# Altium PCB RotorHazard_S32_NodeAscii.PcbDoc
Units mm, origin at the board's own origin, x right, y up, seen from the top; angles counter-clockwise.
Board outline 34.29 x 33.02 mm, 2 copper layers (Top Layer, Bottom Layer); 2 components, 6 nets, 21 pads, 0 vias.
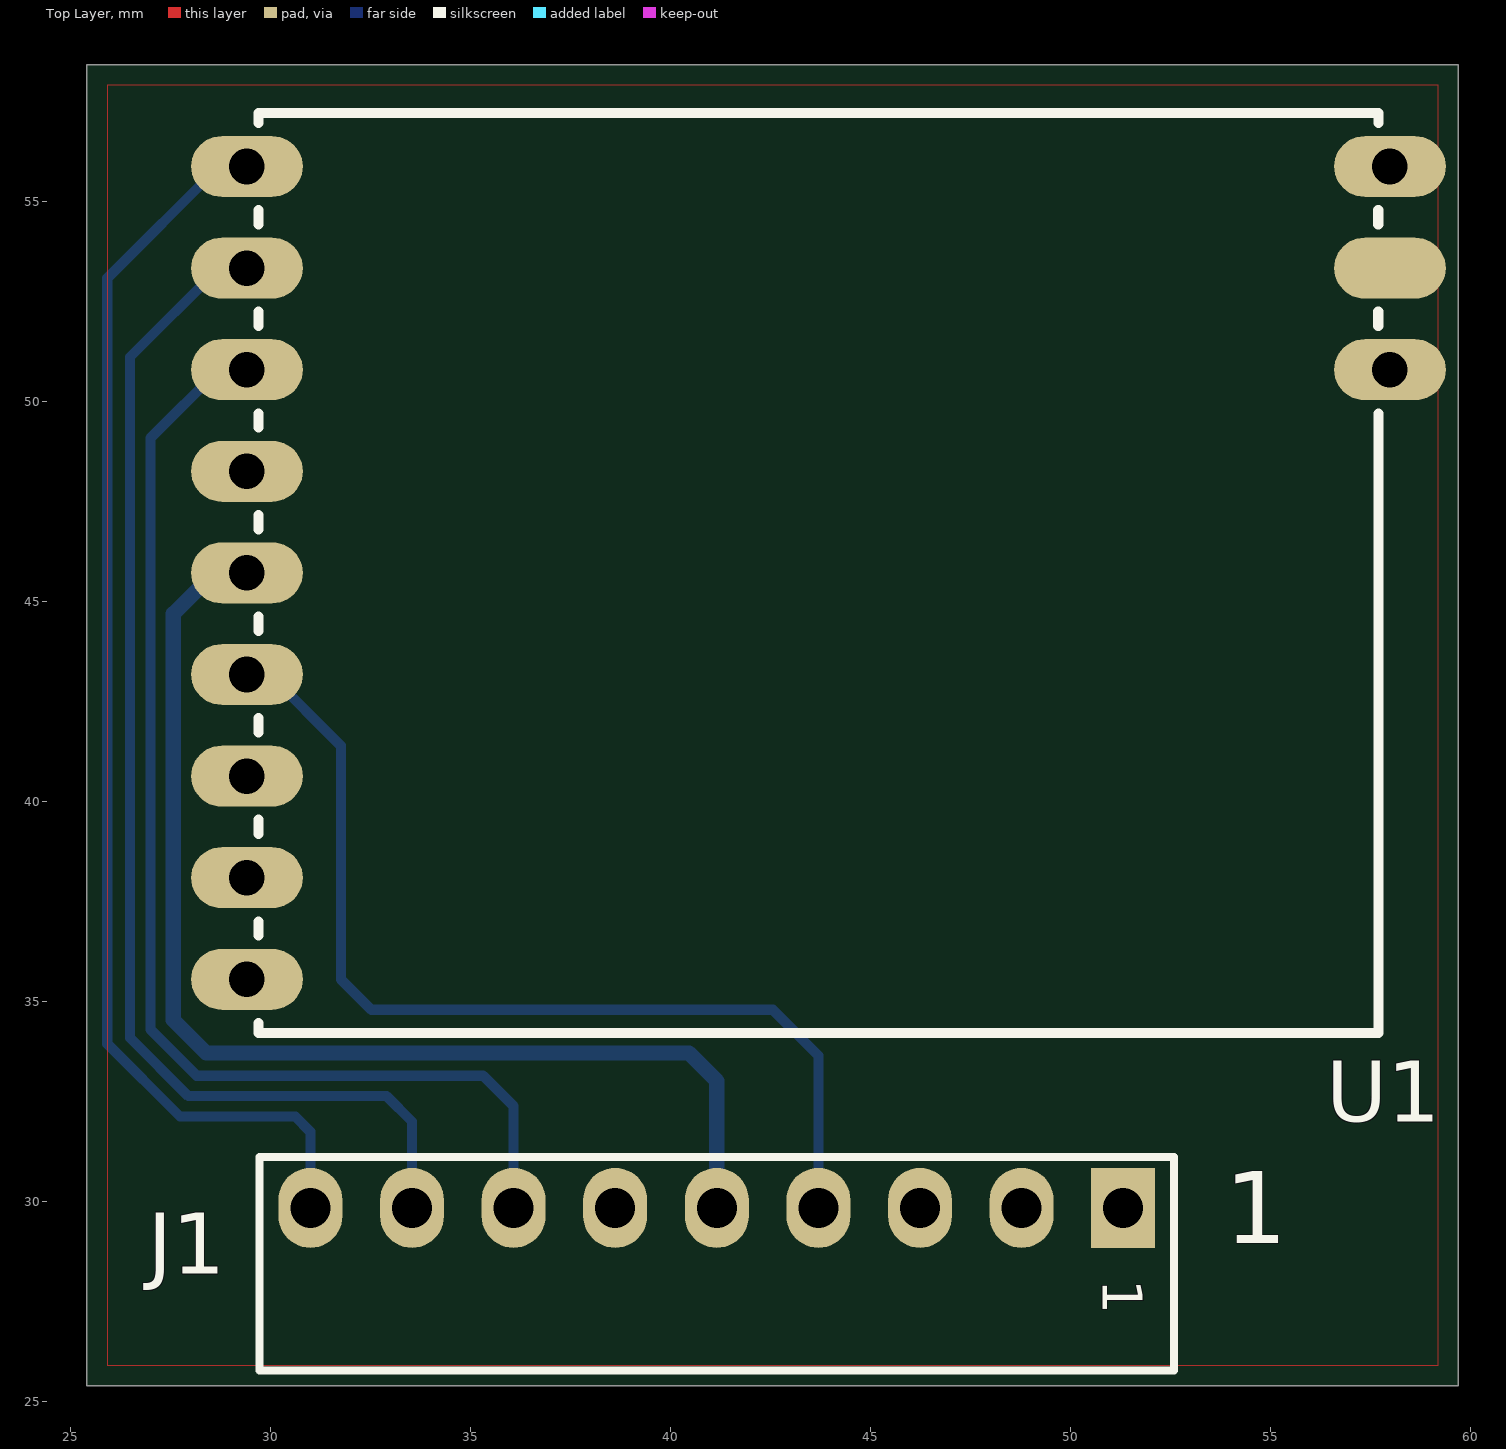
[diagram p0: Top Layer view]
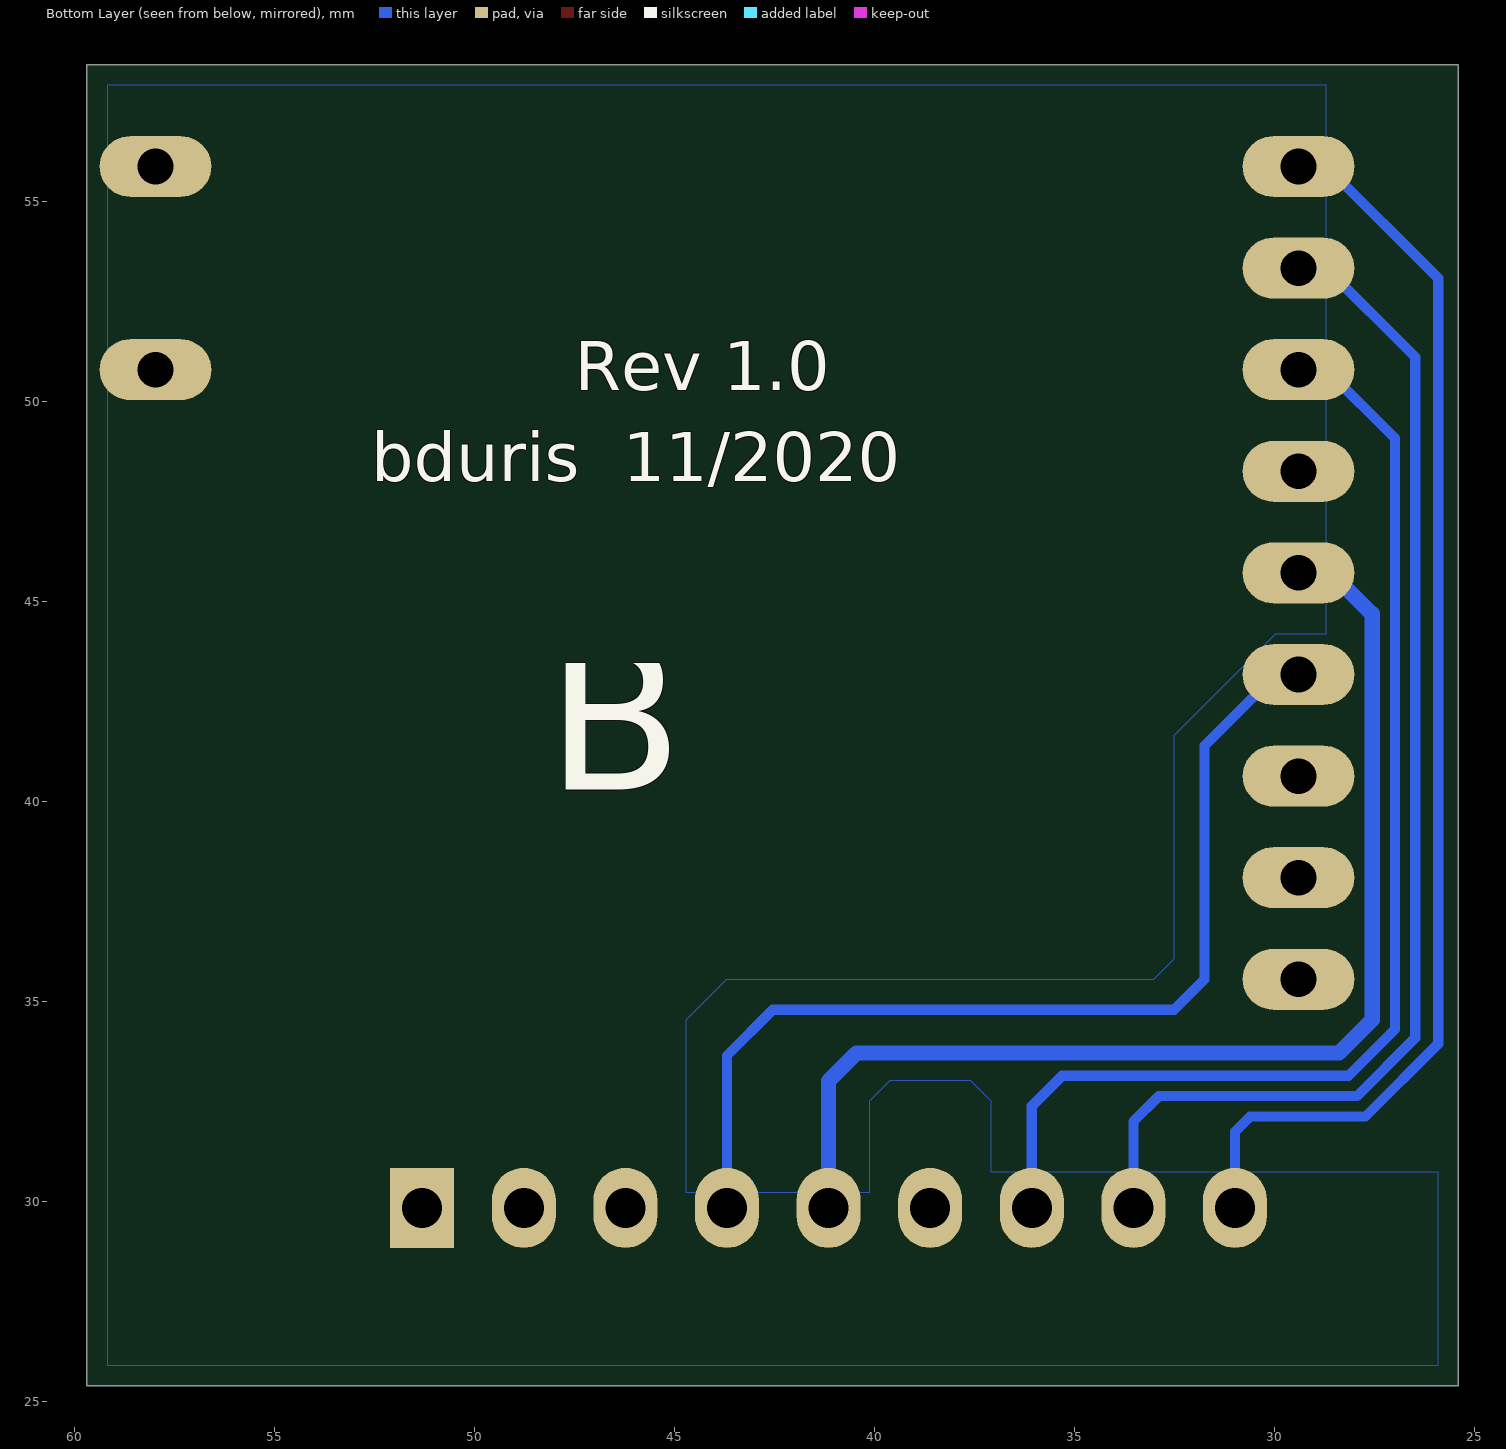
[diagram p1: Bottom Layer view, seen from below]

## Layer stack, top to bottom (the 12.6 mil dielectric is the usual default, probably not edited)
Top Solder: solder mask 0.0102, Solder Resist, Dk 3.5
Top Layer: signal copper 0.0356
Dielectric 1: dielectric 0.32, FR-4, Dk 4.8
Bottom Layer: signal copper 0.0356
Bottom Solder: solder mask 0.0102, Solder Resist, Dk 3.5

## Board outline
25.4,25.4 59.69,25.4 59.69,58.42 25.4,58.42

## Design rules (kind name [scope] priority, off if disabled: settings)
AssemblyTestPointUsage [All] p0: scope1count=1 scope1_0_kind=Board scope1_0_value=Board scope2count=1 scope2_0_kind=Board scope2_0_value=Board commentlength=0
AssemblyTestpoint [All] p0: scope1count=1 scope1_0_kind=Board scope1_0_value=Board scope2count=1 scope2_0_kind=Board scope2_0_value=Board commentlength=0
Clearance [All] p0: scope1count=1 scope1_0_kind=Board scope1_0_value=Board scope2count=1 scope2_0_kind=Board scope2_0_value=Board commentlength=0 gap=0.254
Clearance [All] p1: gap=0.254
ComponentClearance [All] p0: scope1count=1 scope1_0_kind=Board scope1_0_value=Board scope2count=1 scope2_0_kind=Board scope2_0_value=Board commentlength=0 gap=0.254 collisioncheckmode=3
DiffPairsRouting [All] p0: scope1count=1 scope1_0_kind=Board scope1_0_value=Board scope2count=1 scope2_0_kind=Board scope2_0_value=Board commentlength=0
FabricationTestPointUsage [All] p0: scope1count=1 scope1_0_kind=Board scope1_0_value=Board scope2count=1 scope2_0_kind=Board scope2_0_value=Board commentlength=0 valid=0 allowmultiple=FALSE
FabricationTestpoint [All] p0: scope1count=1 scope1_0_kind=Board scope1_0_value=Board scope2count=1 scope2_0_kind=Board scope2_0_value=Board commentlength=0 side=3 testpointundercomponent=TRUE minsize=1.016 maxsize=2.54 preferedsize=1.524 minholesize=0 maxholesize=1.016 preferedholesize=0.813 testpointgrid=0.025
FanoutControl Fanout_Default [All] p0: scope1count=1 scope1_0_kind=Board scope1_0_value=Board scope2count=1 scope2_0_kind=Board scope2_0_value=Board commentlength=30 // Fanout_Default (Default Rule)
FanoutControl Fanout_Small [All] p0 off: scope1count=1 scope1_0_kind=Board scope1_0_value=Board scope2count=1 scope2_0_kind=Board scope2_0_value=Board commentlength=84 // Protel DXP Scope 1 Expression Was: (CompPinCount < 5)   Fanout_Small (Default Rule)
FanoutControl Fanout_SOIC [All] p0 off: scope1count=1 scope1_0_kind=Board scope1_0_value=Board scope2count=1 scope2_0_kind=Board scope2_0_value=Board commentlength=71 // Protel DXP Scope 1 Expression Was: IsSOIC   Fanout_SOIC (Default Rule)
FanoutControl Fanout_LCC [All] p0 off: scope1count=1 scope1_0_kind=Board scope1_0_value=Board scope2count=1 scope2_0_kind=Board scope2_0_value=Board commentlength=69 // Protel DXP Scope 1 Expression Was: IsLCC   Fanout_LCC (Default Rule)
FanoutControl Fanout_BGA [All] p0 off: scope1count=1 scope1_0_kind=Board scope1_0_value=Board scope2count=1 scope2_0_kind=Board scope2_0_value=Board commentlength=69 // Protel DXP Scope 1 Expression Was: IsBGA   Fanout_BGA (Default Rule)
Height [All] p0: scope1count=1 scope1_0_kind=Board scope1_0_value=Board scope2count=1 scope2_0_kind=Board scope2_0_value=Board commentlength=0
HoleSize [All] p0: scope1count=1 scope1_0_kind=Board scope1_0_value=Board scope2count=1 scope2_0_kind=Board scope2_0_value=Board commentlength=0 absolutevalues=TRUE maxlimit=2.54 minlimit=0.025 maxpercent=80.000 minpercent=20.000
HoleToHoleClearance [All] p0: scope1count=1 scope1_0_kind=Board scope1_0_value=Board scope2count=1 scope2_0_kind=Board scope2_0_value=Board commentlength=0
LayerPairs [All] p0: scope1count=1 scope1_0_kind=Board scope1_0_value=Board scope2count=1 scope2_0_kind=Board scope2_0_value=Board commentlength=0 enforce=TRUE
MinimumSolderMaskSliver [All] p0: scope1count=1 scope1_0_kind=Board scope1_0_value=Board scope2count=1 scope2_0_kind=Board scope2_0_value=Board commentlength=0
NetAntennae [All] p0: scope1count=1 scope1_0_kind=Board scope1_0_value=Board scope2count=1 scope2_0_kind=Board scope2_0_value=Board commentlength=0
PasteMaskExpansion [All] p0: scope1count=1 scope1_0_kind=Board scope1_0_value=Board scope2count=1 scope2_0_kind=Board scope2_0_value=Board commentlength=0 expansion=0
PlaneClearance [All] p0: scope1count=1 scope1_0_kind=Board scope1_0_value=Board scope2count=1 scope2_0_kind=Board scope2_0_value=Board commentlength=0 clearance=0.508
PlaneConnect [All] p0: scope1count=1 scope1_0_kind=Board scope1_0_value=Board scope2count=1 scope2_0_kind=Board scope2_0_value=Board commentlength=0 planeconnectstyle=Relief reliefexpansion=0.508 reliefentries=4 reliefconductorwidth=0.254 reliefairgap=0.254
PolygonConnect [All] p0: scope1count=1 scope1_0_kind=Board scope1_0_value=Board scope2count=1 scope2_0_kind=Board scope2_0_value=Board commentlength=0 connectstyle=Relief reliefconductorwidth=0.254 reliefentries=4 polygonreliefangle="90 Angle"
PolygonConnect [All] p1: connectstyle=Relief reliefconductorwidth=0.254 reliefentries=4 polygonreliefangle="90 Angle" airgapwidth=0.254
RoutingCorners [All] p0: scope1count=1 scope1_0_kind=Board scope1_0_value=Board scope2count=1 scope2_0_kind=Board scope2_0_value=Board commentlength=0 cornerstyle=45-Degree minsetback=2.54 maxsetback=2.54
RoutingLayers [All] p0: scope1count=1 scope1_0_kind=Board scope1_0_value=Board scope2count=1 scope2_0_kind=Board scope2_0_value=Board commentlength=0 top layer=Automatic bottom layer=Automatic
RoutingPriority [All] p0: scope1count=1 scope1_0_kind=Board scope1_0_value=Board scope2count=1 scope2_0_kind=Board scope2_0_value=Board commentlength=0
RoutingTopology [All] p0: scope1count=1 scope1_0_kind=Board scope1_0_value=Board scope2count=1 scope2_0_kind=Board scope2_0_value=Board commentlength=0 topology=Shortest
RoutingVias [All] p0: scope1count=1 scope1_0_kind=Board scope1_0_value=Board scope2count=1 scope2_0_kind=Board scope2_0_value=Board commentlength=0 holewidth=0.711 width=1.27 viastyle="Through Hole" minholewidth=0.711 minwidth=1.27 maxholewidth=0.711 maxwidth=1.27
RoutingVias [All] p1: holewidth=0.711 width=1.27 viastyle="Through Hole" minholewidth=0.711 minwidth=1.27 maxholewidth=0.711 maxwidth=1.27
ShortCircuit [All] p0: scope1count=1 scope1_0_kind=Board scope1_0_value=Board scope2count=1 scope2_0_kind=Board scope2_0_value=Board commentlength=0 allowed=FALSE
SilkToBoardRegionClearance [All] p0: scope1count=1 scope1_0_kind=Board scope1_0_value=Board scope2count=1 scope2_0_kind=Board scope2_0_value=Board commentlength=0
SilkToSilkClearance [All] p0: scope1count=1 scope1_0_kind=Board scope1_0_value=Board scope2count=1 scope2_0_kind=Board scope2_0_value=Board commentlength=0
SilkToSolderMaskClearance [All] p0 off: scope1count=1 scope1_0_kind=Board scope1_0_value=Board scope2count=1 scope2_0_kind=Board scope2_0_value=Board commentlength=44 // Protel DXP Scope 1 Expression Was: IsPad
SilkToSolderMaskClearance [IsPad] p1: minsilkscreentomaskgap=0.152 clearancetoexposedcopper=TRUE
SolderMaskExpansion [All] p0: scope1count=1 scope1_0_kind=Board scope1_0_value=Board scope2count=1 scope2_0_kind=Board scope2_0_value=Board commentlength=0 expansion=0.102
SolderMaskExpansion [All] p1: expansion=0.102
UnRoutedNet [All] p0: scope1count=1 scope1_0_kind=Board scope1_0_value=Board scope2count=1 scope2_0_kind=Board scope2_0_value=Board commentlength=0
UnpouredPolygon [All] p0: scope1count=1 scope1_0_kind=Board scope1_0_value=Board scope2count=1 scope2_0_kind=Board scope2_0_value=Board commentlength=0
Width [All] p0: scope1count=1 scope1_0_kind=Board scope1_0_value=Board scope2count=1 scope2_0_kind=Board scope2_0_value=Board commentlength=0 maxlimit=0.889 minlimit=0.254 preferedwidth=0.254
Width [All] p1: maxlimit=0.889 minlimit=0.254 preferedwidth=0.254 minimp=50.000000 maximp=50.000000 favimp=50.000000
29 further rules are at their usual default settings.

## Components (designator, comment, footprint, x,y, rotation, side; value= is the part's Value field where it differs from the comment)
J1 "HDR 1X9 RA" "HDR 1X9 2.54mm RA" 51.308,29.845 r270 top
U1 "RX5808" RX5808_MULTI 43.688,45.72 r180 top

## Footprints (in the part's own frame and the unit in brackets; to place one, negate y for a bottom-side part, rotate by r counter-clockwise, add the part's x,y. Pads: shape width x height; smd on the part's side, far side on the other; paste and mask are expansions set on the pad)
"HDR 1X9 2.54mm RA" [mm]
  rect 2x1.6 hole 1: 1(0,0)
  oval 2x1.6 hole 1: 2(0,-2.54) 3(0,-5.08) 4(0,-7.62) 5(0,-10.16) 6(0,-12.7) 7(0,-15.24) 8(0,-17.78) 9(0,-20.32)
  silkscreen extent -1.27,-21.59 4.06,1.27
RX5808_MULTI [mil] "RX5808 Module with multi-layer pads"
  oval 110x60 hole 35: 1(562.5,-400) 2(562.5,-300) 3(562.5,-200) 4(562.5,-100) 5(562.5,0) 6(562.5,100) 7(562.5,200) 8(562.5,300) 9(562.5,400) 10(-562.5,-200) 12(-562.5,-400)
  oval 110x60 smd: 11(-562.5,-300)
  silkscreen extent -551,-453 551,453

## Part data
J1: library part 649-1012937990904BLF, "9-Pin RA Header Thru-Hole"
U1: library part RX5808_MULTI, "RX5808 with multi-layer pads"

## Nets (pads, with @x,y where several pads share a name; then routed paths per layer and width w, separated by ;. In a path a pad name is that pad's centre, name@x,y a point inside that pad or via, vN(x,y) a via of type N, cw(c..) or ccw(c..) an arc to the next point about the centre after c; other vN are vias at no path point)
+5V_RX: J1.5 U1.5 | length 29.8
  Bottom Layer w0.381: U1.5 28.583,45.72 27.559,44.696 27.559,34.544 28.384,33.718 40.45,33.718 41.148,33.02 J1.5
GND: J1.1 J1.6 U1.4 U1.9 U1.10 U1.12
RSSI: J1.4 U1.6 | length 25.5
  Bottom Layer w0.254: U1.6 29.972,43.18 31.75,41.402 31.75,35.56 32.512,34.798 42.545,34.798 43.688,33.655 J1.4
SPI_CLK: J1.7 U1.3 | length 30.3
  Bottom Layer w0.254: U1.3 28.702,50.8 26.987,49.085 26.987,34.307 28.148,33.147 35.306,33.147 36.068,32.385 J1.7
SPI_DAT: J1.9 U1.1 | length 31.7
  Bottom Layer w0.254: U1.1 28.702,55.88 25.908,53.086 25.908,33.95 27.727,32.131 30.607,32.131 30.988,31.75 J1.9
SPI_LE: J1.8 U1.2 | length 30.9
  Bottom Layer w0.254: U1.2 28.702,53.34 26.479,51.117 26.479,34.097 27.937,32.639 32.893,32.639 33.528,32.004 J1.8
pads on no net: J1.2 J1.3 U1.7 U1.8 U1.11

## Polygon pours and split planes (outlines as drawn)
GND on Top Layer "GND_TOP" (solid, pour order 0): 25.908,57.912 25.908,25.908 59.182,25.908 59.182,57.912 25.908,57.912
GND on Bottom Layer "GND_BOT" (solid, pour order 2): 28.702,57.912 59.182,57.912 59.182,25.908 25.908,25.908 25.908,30.734 37.084,30.734 37.084,32.512 37.592,33.02 39.624,33.02 40.132,32.512 40.132,30.226 44.704,30.226 44.704,34.544 43.688,35.56 33.02,35.56 32.512,36.068 32.512,41.656 29.972,44.196 28.702,44.196

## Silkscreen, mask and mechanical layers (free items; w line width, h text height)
Top Overlay:
  text "1" at 53.848,28.956 h1.8
Bottom Overlay:
  text "Rev 1.0" at 47.498,50.292 h1.22
  text "bduris  11/2020" at 52.578,48.006 h1.22
  text "B" at 48.2,38.4 h10
Board Outline:
  the board outline again, w0.15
